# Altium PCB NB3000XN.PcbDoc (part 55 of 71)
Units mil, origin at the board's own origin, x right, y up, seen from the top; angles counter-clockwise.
Board outline 9527.56 x 6929.77 mil, 6 copper layers (Top Layer, GND+SHIELD, MidLayer1, MidLayer2, P2 - 3V3+5V0, Bottom Layer), stack 62.375 mil thick; 832 components, 1027 nets, 4655 pads, 4981 vias.
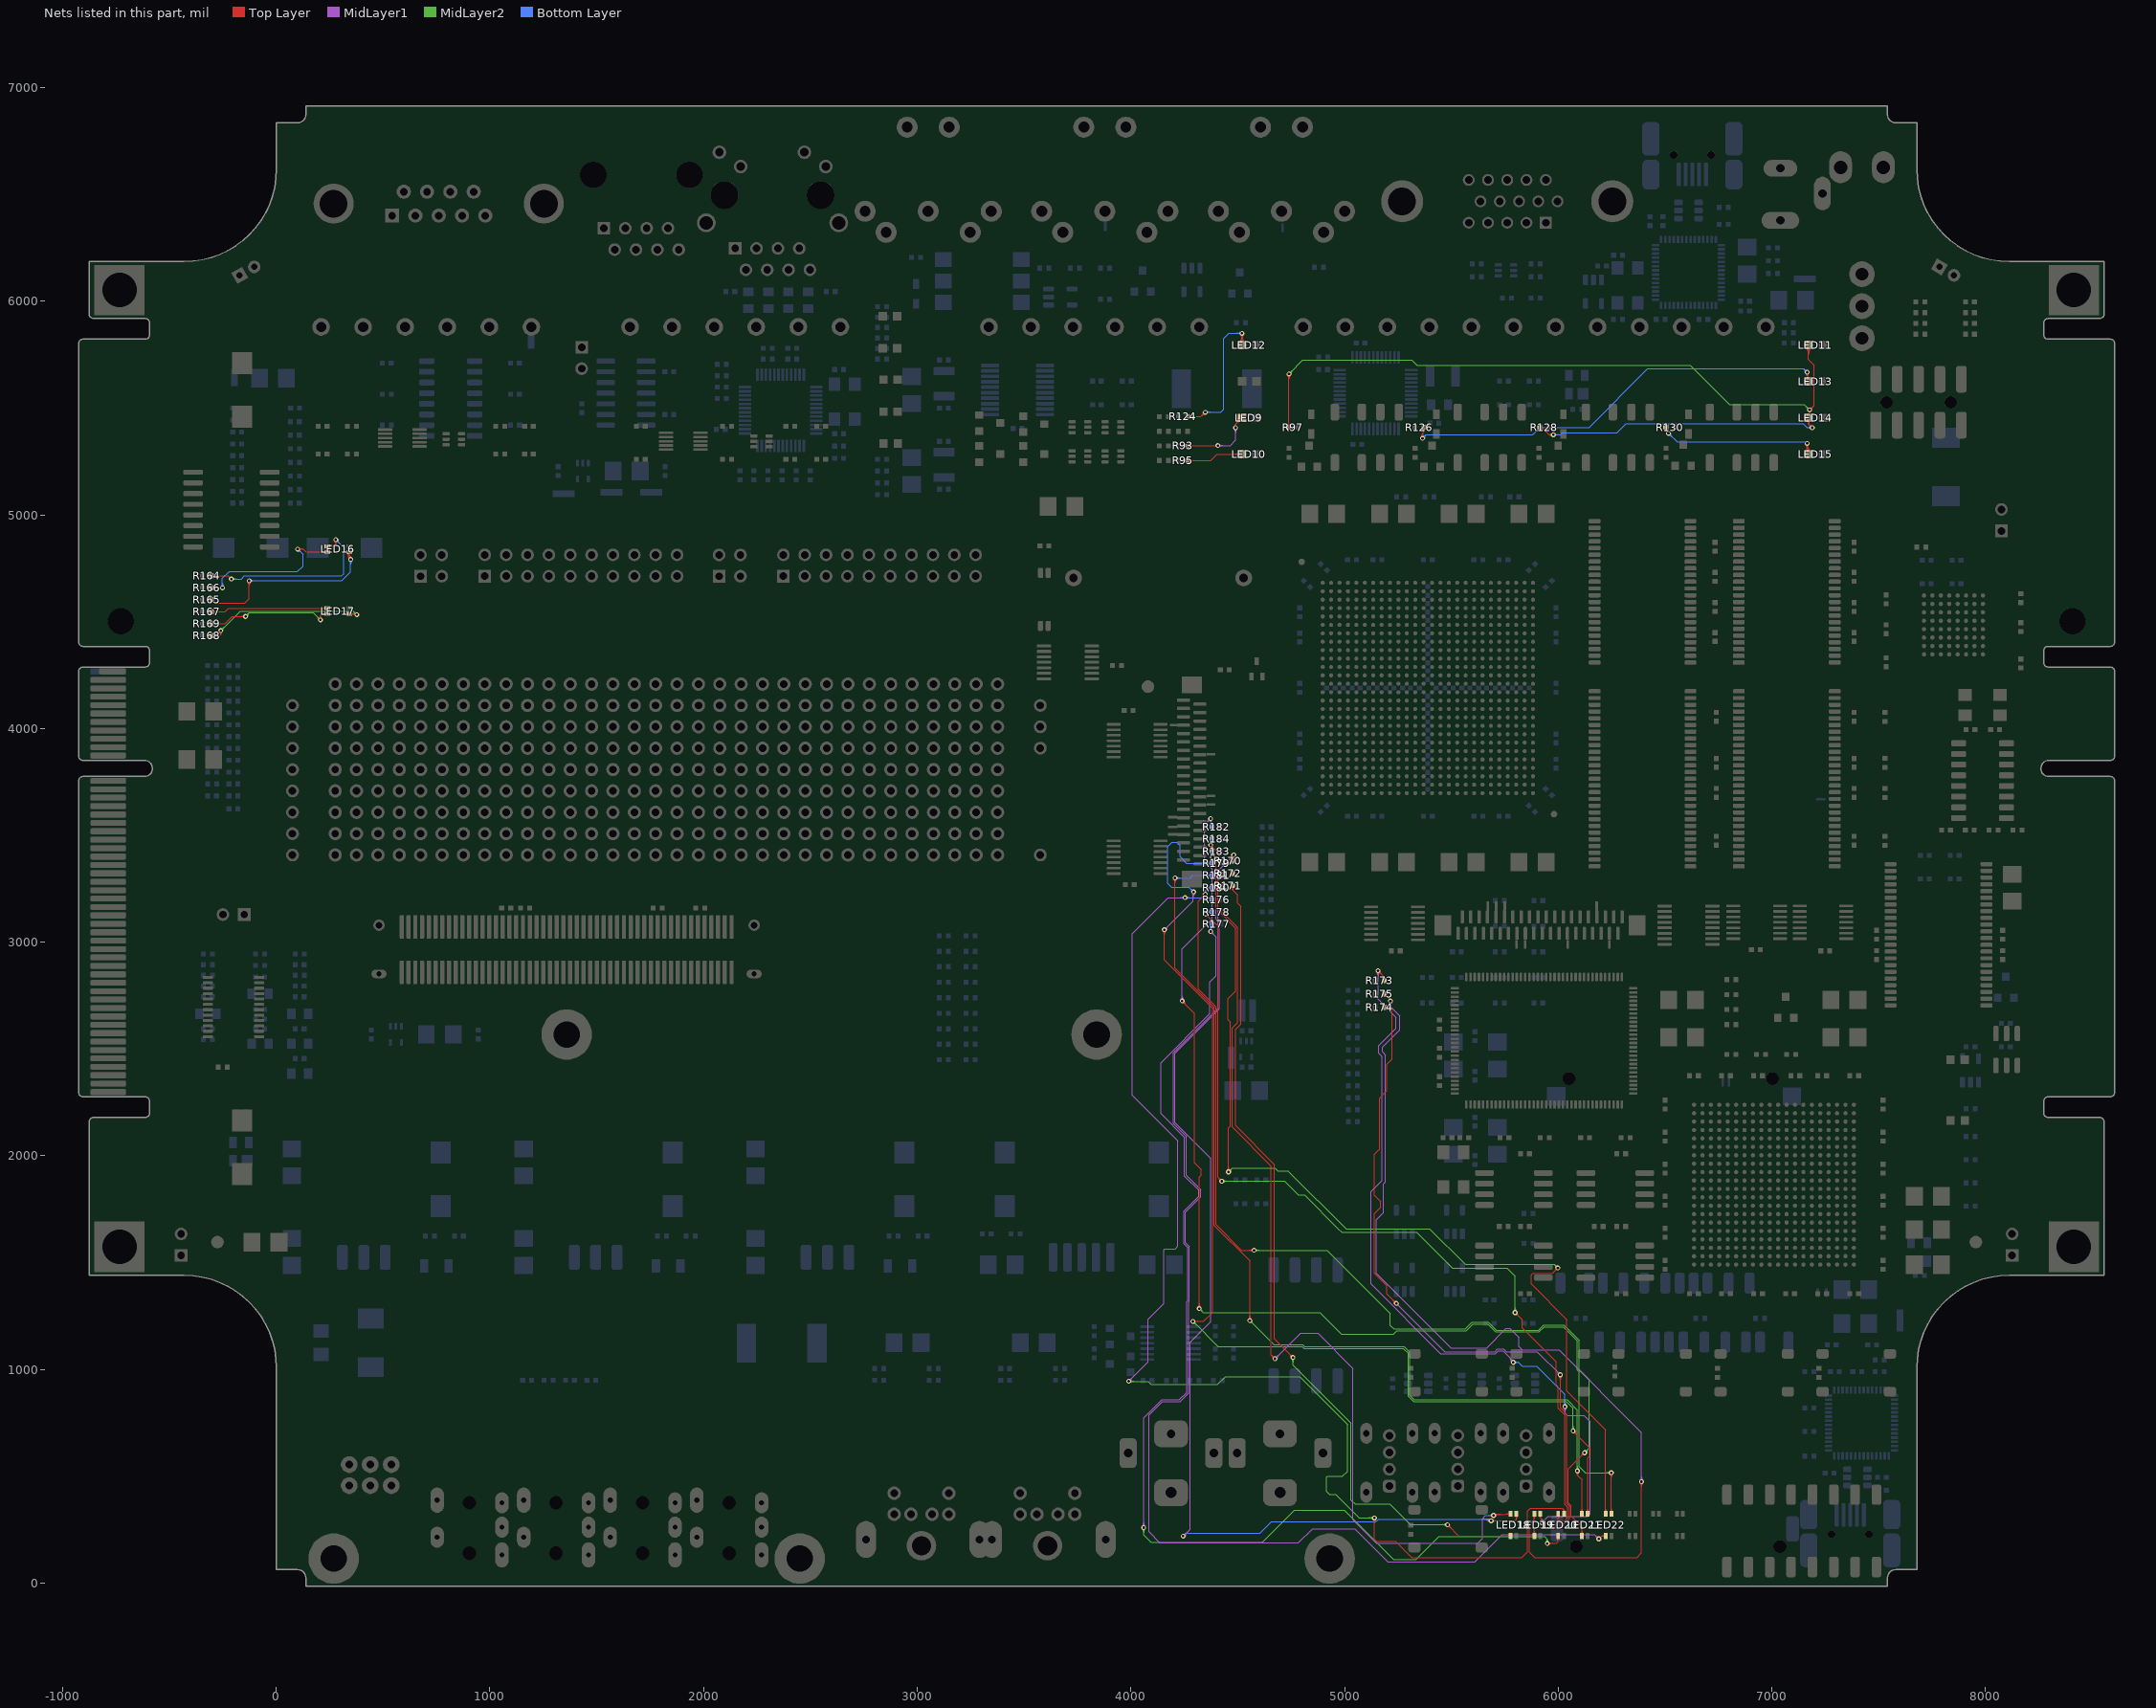
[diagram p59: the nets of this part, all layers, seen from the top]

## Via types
v1: diameter 23, hole 11.81, Top Layer to Bottom Layer, 3672 vias
v2: diameter 26, hole 11.81, Top Layer to Bottom Layer, 461 vias
v3: diameter 19, hole 11.81, Top Layer to Bottom Layer, tented both sides, 396 vias
v4: diameter 23.62, hole 11.81, Top Layer to Bottom Layer, 288 vias
v5: diameter 20, hole 11.81, Top Layer to Bottom Layer, 91 vias
v6: diameter 23, hole 11.81, Top Layer to Bottom Layer, tented both sides, 50 vias
v7: diameter 31, hole 11.81, Top Layer to Bottom Layer, 15 vias
v8: diameter 27.56, hole 11.81, Top Layer to Bottom Layer, tented both sides, 4 vias
v9: diameter 29, hole 11.81, Top Layer to Bottom Layer, 3 vias
v10: diameter 21, hole 11.81, Top Layer to Bottom Layer, 1 vias

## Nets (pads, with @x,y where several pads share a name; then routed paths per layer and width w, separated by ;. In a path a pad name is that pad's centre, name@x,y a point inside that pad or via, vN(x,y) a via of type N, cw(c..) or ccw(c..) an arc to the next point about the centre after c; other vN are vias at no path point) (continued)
NetLED9_2: LED9.2 R93.2 | length 677
  Top Layer w4: R93.2@4266.18,5323.33 4390.86,5323.33 4392.57,5325.04 v1(4406.86,5325.04) ; R93.2@4269.94,5319.57 cw(c4279.02,5310.49) 4279.02,5323.33 cw(c4279.02,5336.18) R93.2@4269.94,5327.09 ; R93.2@4272.77,5316.74 cw(c4288.68,5300.84) 4288.68,5323.33 cw(c4288.68,5345.83) R93.2@4272.77,5329.92 ; v1(4490.19,5408.37) 4490.19,5424.22 LED9.2@4520.49,5454.52 ; LED9.2@4502.8,5454.52 cw(c4460.1,5454.52) 4490.29,5424.33 cw(c4520.49,5394.14) LED9.2@4520.49,5436.83 ; LED9.2@4506.8,5454.52 cw(c4473.76,5454.52) 4497.12,5431.15 cw(c4520.49,5407.79) LED9.2@4520.49,5440.83 ; LED9.2@4510.8,5454.52 cw(c4487.42,5454.52) 4503.95,5437.98 cw(c4520.49,5421.45) LED9.2@4520.49,5444.83
  MidLayer1 w4: v1(4406.86,5325.04) 4465.04,5325.04 4490.19,5350.19 v1(4490.19,5408.37) ; v1@4410.75,5321.15 cw(c4420.14,5311.76) 4420.14,5325.04 cw(c4420.14,5338.32) v1@4410.75,5328.93 ; v1@4413.57,5318.32 cw(c4429.79,5302.11) 4429.79,5325.04 cw(c4429.79,5347.98) v1@4413.57,5331.76 ; v1@4483.47,5401.66 cw(c4467.26,5385.44) 4490.19,5385.44 cw(c4513.13,5385.44) v1@4496.91,5401.66 ; v1@4486.3,5404.49 cw(c4476.91,5395.1) 4490.19,5395.1 cw(c4503.47,5395.1) v1@4494.08,5404.49
NetLED10_2: LED10.2 R95.2 | length 477.6
  Top Layer w4: R95.2@4266.18,5255 4373.52,5255 4402.65,5284.13 LED10.2@4520.49,5284.13 ; R95.2@4269.94,5251.24 cw(c4279.02,5242.16) 4279.02,5255 cw(c4279.02,5267.84) R95.2@4269.94,5258.76 ; R95.2@4272.77,5248.41 cw(c4288.68,5232.5) 4288.68,5255 cw(c4288.68,5277.5) R95.2@4272.77,5261.59 ; LED10.2@4507.98,5271.63 ccw(c4477.79,5241.44) 4477.79,5284.13 ccw(c4477.79,5326.83) LED10.2@4507.98,5296.64 ; LED10.2@4510.81,5274.45 ccw(c4487.45,5251.09) 4487.45,5284.13 ccw(c4487.45,5317.17) LED10.2@4510.81,5293.81 ; LED10.2@4513.64,5277.28 ccw(c4497.1,5260.75) 4497.1,5284.13 ccw(c4497.1,5307.51) LED10.2@4513.64,5290.98
NetLED11_2: LED11.2 R97.2 | length 3566.2
  Top Layer w4: R97.2@4732.23,5417.08 ccw(c4713.01,5436.3) 4740.19,5436.3 ; v1@4733.47,5652.66 cw(c4717.26,5636.44) 4740.19,5636.44 cw(c4763.13,5636.44) v1@4746.91,5652.66 ; R97.2@4735.06,5414.25 ccw(c4722.67,5426.64) 4740.19,5426.64 ; v1@4736.3,5655.49 cw(c4726.91,5646.1) 4740.19,5646.1 cw(c4753.47,5646.1) v1@4744.08,5655.49 ; R97.2@4738.82,5410 4740.19,5411.37 v1(4740.19,5659.37) ; 4740.19,5429.68 ccw(c4758.01,5429.68) R97.2@4745.41,5417.08 ; LED11.2@7159.69,5782.78 cw(c7129.5,5752.59) 7172.19,5752.59 cw(c7214.89,5752.59) LED11.2@7184.7,5782.78 ; LED11.2@7162.52,5785.61 cw(c7139.15,5762.25) 7172.19,5762.25 cw(c7205.23,5762.25) LED11.2@7181.87,5785.61 ; LED11.2@7165.34,5788.44 cw(c7148.81,5771.9) 7172.19,5771.9 cw(c7195.57,5771.9) LED11.2@7179.04,5788.44 ; LED11.2@7172.19,5795.28 7172.19,5726.33 7198.52,5700 7198.52,5513.37 v1(7176.86,5491.71) ; v1@7176.86,5497.21 ccw(c7176.86,5510.49) 7186.25,5501.1 ccw(c7195.64,5491.71) v1@7182.36,5491.71 ; v1@7176.86,5501.21 ccw(c7176.86,5524.14) 7193.07,5507.93 ccw(c7209.29,5491.71) v1@7186.36,5491.71
  MidLayer2 w4: v1(4740.19,5659.37) 4775.41,5694.59 ; v1@4740.19,5664.87 ccw(c4740.19,5678.15) 4749.58,5668.76 ccw(c4758.97,5659.37) v1@4745.69,5659.37 ; v1@4740.19,5668.87 ccw(c4740.19,5691.81) 4756.41,5675.59 ccw(c4772.63,5659.37) v1@4749.69,5659.37 ; 4775,5695 4804.71,5724.71 4875,5724.71 5315.52,5724.71 5340.19,5700.04 6617.58,5700.04 6784.87,5532.75 6800.58,5517.04 7151.52,5517.04 v1(7176.86,5491.71) ; v1@7167.36,5491.71 ccw(c7144.42,5491.71) 7160.64,5507.93 ccw(c7176.86,5524.14) v1@7176.86,5501.21 ; v1@7171.36,5491.71 ccw(c7158.08,5491.71) 7167.47,5501.1 ccw(c7176.86,5510.49) v1@7176.86,5497.21
NetLED12_2: LED12.2 R124.2 | length 1107.1
  Top Layer w4: R124.2@4266.18,5460 4328.15,5460 v1(4348.52,5480.37) ; R124.2@4269.94,5456.24 cw(c4279.02,5447.16) 4279.02,5460 cw(c4279.02,5472.84) R124.2@4269.94,5463.76 ; R124.2@4272.77,5453.41 cw(c4288.68,5437.5) 4288.68,5460 cw(c4288.68,5482.5) R124.2@4272.77,5466.59 ; v1@4339.02,5480.37 cw(c4316.09,5480.37) 4332.31,5464.16 cw(c4348.52,5447.94) v1@4348.52,5470.87 ; v1@4343.02,5480.37 cw(c4329.75,5480.37) 4339.14,5470.99 cw(c4348.52,5461.6) v1@4348.52,5474.87 ; LED12.2@4507.98,5807.8 ccw(c4476.82,5838.96) v1@4520.89,5838.96 ; LED12.2@4510.81,5804.97 ccw(c4486.47,5829.3) 4520.89,5829.3 ; v1@4513.28,5843.28 cw(c4494.92,5824.92) 4520.89,5824.92 ; LED12.2@4513.64,5802.14 ccw(c4496.13,5819.65) 4520.89,5819.65 ; v1@4516.11,5846.11 cw(c4504.58,5834.58) 4520.89,5834.58 ; v1(4520,5850) 4520.89,5849.11 4520.89,5789.18 4520.49,5789.18 LED12.2@4520.49,5795.29 ; 4520.89,5817.7 ccw(c4542.89,5817.7) LED12.2@4527.33,5802.14 ; 4520.89,5827.35 ccw(c4552.55,5827.35) LED12.2@4530.16,5804.97 ; 4520.89,5829.21 cw(c4540.79,5829.21) v1@4526.72,5843.28 ; 4520.89,5837.01 ccw(c4562.21,5837.01) LED12.2@4532.99,5807.8
  Bottom Layer w4: v1(4348.52,5480.37) 4420.41,5480.37 4435.04,5495 4435.04,5825.04 4460,5850 v1(4520,5850) ; v1@4352.41,5476.49 cw(c4361.8,5467.1) 4361.8,5480.37 cw(c4361.8,5493.65) v1@4352.41,5484.26 ; v1@4355.24,5473.66 cw(c4371.46,5457.44) 4371.46,5480.37 cw(c4371.46,5503.31) v1@4355.24,5487.09 ; v1@4513.28,5843.28 ccw(c4497.06,5827.06) 4497.06,5850 ccw(c4497.06,5872.93) v1@4513.28,5856.72 ; v1@4516.11,5846.11 ccw(c4506.72,5836.72) 4506.72,5850 ccw(c4506.72,5863.28) v1@4516.11,5853.89
NetLED13_2: LED13.2 R126.2 | length 2359.2
  Top Layer w4: v1@5358.47,5365.09 ccw(c5342.26,5381.31) 5365.19,5381.31 ccw(c5388.13,5381.31) v1@5371.91,5365.09 ; v1@5361.3,5362.26 ccw(c5351.91,5371.65) 5365.19,5371.65 ccw(c5378.47,5371.65) v1@5369.08,5362.26 ; R126.2@5364.98,5402.56 cw(c5352.61,5388.7) 5371.18,5388.7 ; v1(5365.19,5358.37) 5365.19,5382.71 5371.18,5388.7 ; R126.2@5367.64,5405.54 cw(c5360.58,5397.63) 5371.18,5397.63 cw(c5381.78,5397.63) R126.2@5374.72,5405.54 ; R126.2@5371.18,5410 5371.18,5388.7 ; R126.2@5377.39,5402.56 ccw(c5389.76,5388.7) 5371.18,5388.7 ; v1@7160.64,5659.37 cw(c7156.47,5651.71) 7165.19,5651.71 ; v1(7165.19,5667.71) 7165.19,5651.71 ; 7165.44,5651.46 cw(c7152.53,5638.55) LED13.2@7167.52,5628.14 ; 7168.82,5648.08 cw(c7156.52,5635.78) LED13.2@7170.81,5625.86 ; v1@7169.74,5659.37 ccw(c7173.91,5651.71) 7165.19,5651.71 ; LED13.2@7170.2,5642.47 ccw(c7169.94,5644.71) 7172.19,5644.71 ; LED13.2@7172.19,5624.9 7172.19,5644.71 ; 7172.21,5644.69 cw(c7160.52,5633.01) LED13.2@7174.09,5623.58 ; LED13.2@7174.19,5642.47 cw(c7174.44,5644.71) 7172.19,5644.71 ; 7165.19,5651.71 7172.19,5644.71
  Bottom Layer w4: v1(5365.19,5358.37) 5381.86,5375.04 5881.86,5375.04 5916.19,5409.37 6144.37,5409.37 6419.04,5684.04 6825,5684.04 7148.86,5684.04 v1(7165.19,5667.71) ; v1@5365.19,5363.87 ccw(c5365.19,5377.15) 5374.58,5367.76 ccw(c5383.97,5358.37) v1@5370.69,5358.37 ; v1@5365.19,5367.87 ccw(c5365.19,5390.81) 5381.41,5374.59 ccw(c5397.63,5358.37) v1@5374.69,5358.37 ; v1@7155.69,5667.71 ccw(c7132.76,5667.71) 7148.97,5683.93 ccw(c7165.19,5700.14) v1@7165.19,5677.21 ; v1@7159.69,5667.71 ccw(c7146.41,5667.71) 7155.8,5677.1 ccw(c7165.19,5686.49) v1@7165.19,5673.21
NetLED14_2: LED14.2 R128.2 | length 1728.7
  Top Layer w4: R128.2@5913.82,5400.19 cw(c5913.82,5357) 5944.36,5387.54 ; R128.2@5913.82,5404.19 cw(c5913.82,5370.65) 5937.53,5394.37 ; R128.2@5913.82,5408.19 cw(c5913.82,5384.31) 5930.7,5401.19 ; R128.2@5913.82,5410 5921.9,5410 5956.86,5375.04 ; v1@5969.9,5368.95 ccw(c5956.86,5358.03) 5956.86,5375.04 ; v1@5969.9,5381.14 cw(c5956.86,5392.05) 5956.86,5375.04 ; v1@5972.97,5371.51 ccw(c5965.42,5365.19) 5965.42,5375.04 ccw(c5965.42,5384.89) v1@5972.97,5378.57 ; v1(5977.19,5375.04) 5956.86,5375.04 ; LED14.2@7163.87,5438.91 cw(c7156.48,5425.04) 7172.19,5425.04 ; LED14.2@7165.75,5442.44 cw(c7160.03,5431.71) 7172.19,5431.71 cw(c7184.35,5431.71) LED14.2@7178.63,5442.44 ; LED14.2@7172.19,5454.51 7172.19,5425.04 ; v1@7179.36,5408.37 ccw(c7156.42,5408.37) 7172.64,5424.59 ccw(c7188.86,5440.81) v1@7188.86,5417.87 ; LED14.2@7180.51,5438.91 ccw(c7187.91,5425.04) 7172.19,5425.04 ; v1@7183.36,5408.37 ccw(c7170.08,5408.37) 7179.47,5417.76 ccw(c7188.86,5427.15) v1@7188.86,5413.87 ; v1(7188.86,5408.37) 7172.19,5425.04
  Bottom Layer w4: v1(5977.19,5375.04) 6010,5375.04 6020.33,5385.37 6275.52,5385.37 6317.15,5427 7146.37,5427 7165,5408.37 v1(7188.86,5408.37) ; v1@5981.08,5371.15 cw(c5990.47,5361.76) 5990.47,5375.04 cw(c5990.47,5388.32) v1@5981.08,5378.93 ; v1@5983.91,5368.32 cw(c6000.13,5352.11) 6000.13,5375.04 cw(c6000.13,5397.98) v1@5983.91,5381.76 ; v1@7182.14,5401.66 ccw(c7165.92,5385.44) 7165.92,5408.37 ccw(c7165.92,5431.31) v1@7182.14,5415.09 ; v1@7184.97,5404.49 ccw(c7175.58,5395.1) 7175.58,5408.37 ccw(c7175.58,5421.65) v1@7184.97,5412.26
NetLED15_2: LED15.2 R130.2 | length 1035.5
  Top Layer w4: R130.2@6499.48,5401.26 cw(c6495.71,5394.08) 6503.82,5394.08 ; R130.2@6503.82,5410 6503.82,5394.08 ; R130.2@6508.16,5401.26 ccw(c6511.93,5394.08) 6503.82,5394.08 ; v1(6515.86,5382.04) 6503.82,5394.08 ; v1@7158.47,5327.99 cw(c7142.26,5311.77) 7165.19,5311.77 cw(c7188.13,5311.77) v1@7171.91,5327.99 ; LED15.2@7159.69,5296.63 ccw(c7146.4,5309.91) 7165.19,5309.91 ; v1@7161.3,5330.82 cw(c7151.91,5321.43) 7165.19,5321.43 cw(c7178.47,5321.43) v1@7169.08,5330.82 ; 7165.19,5310.12 ccw(c7192.48,5310.12) LED15.2@7175.69,5288.61 ; 7165.19,5318.31 ccw(c7198.87,5318.31) LED15.2@7178.15,5291.76 ; v1@7165.19,5326.51 ccw(c7205.27,5326.51) LED15.2@7180.61,5294.91 ; LED15.2@7172.19,5284.12 7165.19,5291.13 v1(7165.19,5334.71) ccw(c7211.66,5334.71) LED15.2@7183.07,5298.07
  Bottom Layer w4: v1@6515.86,5372.54 cw(c6515.86,5349.61) 6532.07,5365.82 cw(c6548.29,5382.04) v1@6525.36,5382.04 ; v1@6515.86,5376.54 cw(c6515.86,5363.26) 6525.25,5372.65 cw(c6534.64,5382.04) v1@6521.36,5382.04 ; v1(6515.86,5382.04) 6556.52,5341.37 7158.63,5341.37 v1@7165,5335 ; v1@7164.95,5334.95 v1(7165.19,5334.71)
NetLED16_1: LED16.1 R164.1 | length 1124.1
  Top Layer w4: R164.1@-303.82,4715 -224.77,4715 v1(-209.81,4700.04) ; R164.1@-300.06,4711.24 cw(c-290.98,4702.16) -290.98,4715 cw(c-290.98,4727.84) R164.1@-300.06,4718.76 ; R164.1@-297.23,4708.41 cw(c-281.32,4692.5) -281.32,4715 cw(c-281.32,4737.5) R164.1@-297.23,4721.59 ; LED16.1@241.49,4853.78 270.86,4853.78 278.86,4861.78 ; LED16.1@248.38,4848.75 cw(c260.52,4836.61) 260.52,4853.78 ; LED16.1@248.38,4858.45 ccw(c259.66,4869.73) 259.66,4853.78 ; v1@272.21,4877.59 cw(c256.74,4861.78) 278.86,4861.78 ; v1@275.01,4880.44 cw(c266.05,4871.29) 278.86,4871.29 cw(c291.66,4871.29) v1@282.7,4880.44 ; v1(278.86,4884.37) 278.86,4861.78 ; v1@285.5,4877.59 ccw(c300.98,4861.78) 278.86,4861.78
  Bottom Layer w4: v1(-209.81,4700.04) -164,4700.04 -150,4714.04 304.19,4714.04 315.19,4725.04 315.19,4848.04 v1(278.86,4884.37) ; v1@-205.92,4696.15 cw(c-196.53,4686.76) -196.53,4700.04 cw(c-196.53,4713.32) v1@-205.92,4703.93 ; v1@-203.09,4693.32 cw(c-186.87,4677.11) -186.87,4700.04 cw(c-186.87,4722.98) v1@-203.09,4706.76 ; v1@278.86,4874.87 cw(c278.86,4851.94) 295.07,4868.16 cw(c311.29,4884.37) v1@288.36,4884.37 ; v1@278.86,4878.87 cw(c278.86,4865.6) 288.25,4874.99 cw(c297.64,4884.37) v1@284.36,4884.37
NetLED16_3: LED16.3 R165.1 | length 1255.6
  Top Layer w4: R165.1@-303.82,4603 -287.69,4586.87 -148.13,4586.87 -126.48,4608.52 v1(-126.48,4691.71) ; R165.1@-303.73,4597.19 cw(c-303.51,4583.91) R165.1@-294.12,4593.3 ; R165.1@-303.66,4593.19 cw(c-303.29,4570.78) -287.45,4586.63 ; R165.1@-298.5,4602.51 ccw(c-286.85,4602.51) R165.1@-295.09,4594.27 ; R165.1@-294.5,4602.51 ccw(c-273.19,4602.51) -288.26,4587.44 ; v1@-133.19,4684.99 cw(c-149.41,4668.77) -126.48,4668.77 cw(c-103.54,4668.77) v1@-119.76,4684.99 ; v1@-130.36,4687.82 cw(c-139.75,4678.43) -126.48,4678.43 cw(c-113.2,4678.43) v1@-122.59,4687.82 ; LED16.3@332.24,4821.55 cw(c315.61,4804.92) 339.13,4804.92 ; LED16.3@333.47,4820.56 cw(c319.81,4806.91) 339.13,4806.91 cw(c358.44,4806.91) LED16.3@344.79,4820.56 ; LED16.3@335.07,4824.38 cw(c325.26,4814.57) 339.13,4814.57 ; 339.13,4804.3 ccw(c356.58,4804.3) v1@347.18,4789.6 ; 339.13,4811.61 ccw(c361.25,4811.61) v1@349.33,4792.97 ; 339.13,4814.77 cw(c348.72,4814.77) LED16.3@341.94,4821.55 ; LED16.3@339.13,4818.91 ccw(c365.92,4818.91) v1@351.49,4796.34 ; v1(348.52,4791.71) 339.13,4801.1 339.13,4826.22 ccw(c370.59,4826.22) v1@353.64,4799.71
  Bottom Layer w4: v1(-126.48,4691.71) 306.86,4691.71 348.52,4733.37 v1(348.52,4791.71) ; v1@-122.59,4687.82 cw(c-113.2,4678.43) -113.2,4691.71 cw(c-113.2,4704.99) v1@-122.59,4695.6 ; v1@-119.76,4684.99 cw(c-103.54,4668.77) -103.54,4691.71 cw(c-103.54,4714.64) v1@-119.76,4698.43 ; v1@341.81,4784.99 cw(c325.59,4768.77) 348.52,4768.77 cw(c371.46,4768.77) v1@355.24,4784.99 ; v1@344.64,4787.82 cw(c335.25,4778.43) 348.52,4778.43 cw(c361.8,4778.43) v1@352.41,4787.82
NetLED16_4: LED16.4 R166.1 | length 986.6
  Top Layer w4: R166.1@-303.82,4659 -267.48,4659 ; R166.1@-300.06,4655.24 cw(c-290.98,4646.16) -290.98,4659 cw(c-290.98,4671.84) R166.1@-300.06,4662.76 ; R166.1@-297.23,4652.41 cw(c-281.32,4636.5) -281.32,4659 cw(c-281.32,4681.5) R166.1@-297.23,4665.59 ; -266.85,4658.37 v1(-251.48,4658.37) ; v1(100,4840) 100.12,4840.12 125.12,4840.12 139.01,4826.22 LED16.4@241.49,4826.22 ; v1@103.89,4836.11 cw(c113.56,4826.44) 113.56,4840.12 ; v1@103.89,4843.89 ccw(c113,4853) 113,4840.12 ; v1@106.72,4833.28 cw(c123.21,4816.79) 123.21,4840.12 ; v1@106.72,4846.72 ccw(c122.66,4862.66) 122.66,4840.12 ; 216.46,4826.22 ccw(c216.46,4843.73) LED16.4@228.84,4831.35 ; 217.81,4826.22 cw(c217.81,4810.62) LED16.4@228.84,4821.65
  Bottom Layer w4: v1@-258.19,4665.09 ccw(c-274.41,4681.31) -251.48,4681.31 ccw(c-228.54,4681.31) v1@-244.76,4665.09 ; v1@-255.36,4662.26 ccw(c-264.75,4671.65) -251.48,4671.65 ccw(c-238.2,4671.65) v1@-247.59,4662.26 ; v1(-251.48,4658.37) -251.48,4703.52 -220,4735 100,4735 125,4760 125,4815 v1(100,4840) ; v1@100,4830.5 cw(c100,4807.56) 116.22,4823.78 cw(c132.43,4840) v1@109.5,4840 ; v1@100,4834.5 cw(c100,4821.22) 109.39,4830.61 cw(c118.78,4840) v1@105.5,4840
NetLED17_1: LED17.1 R167.1 | length 633.8
  Top Layer w4: R167.1@-303.82,4547 -240,4547 -223.22,4563.78 LED17.1@241.49,4563.78 ; R167.1@-300.06,4543.24 cw(c-290.98,4534.16) -290.98,4547 cw(c-290.98,4559.84) R167.1@-300.06,4550.76 ; R167.1@-297.23,4540.41 cw(c-281.32,4524.5) -281.32,4547 cw(c-281.32,4569.5) R167.1@-297.23,4553.59 ; 216.7,4563.78 cw(c216.7,4546.61) LED17.1@228.84,4558.75 ; 217.56,4563.78 ccw(c217.56,4579.73) LED17.1@228.84,4568.45
NetLED17_3: LED17.3 R168.1 | length 1004
  Top Layer w4: R168.1@-303.82,4435 -265,4435 -259.81,4440.19 ; R168.1@-300.06,4431.24 cw(c-290.98,4422.16) -290.98,4435 cw(c-290.98,4447.84) R168.1@-300.06,4438.76 ; R168.1@-297.23,4428.41 cw(c-281.32,4412.5) -281.32,4435 cw(c-281.32,4457.5) R168.1@-297.23,4441.59 ; v1@-265.24,4450.58 cw(c-272.46,4440.19) -259.81,4440.19 ; v1(-259.81,4458.37) -259.81,4440.19 ; v1@-254.38,4450.58 ccw(c-247.16,4440.19) -259.81,4440.19 ; LED17.3@339.13,4536.22 363.01,4536.22 ; LED17.3@351.79,4531.56 cw(c363.01,4520.38) 363.01,4536.22 ; LED17.3@351.97,4541.05 ccw(c363.01,4551.25) 363.01,4536.22 ; v1(377.19,4533.37) 365.86,4533.37 363.01,4536.22
  MidLayer2 w4: v1(-259.81,4458.37) -168.14,4550.04 -80,4550.04 -50.04,4550 -50,4550.04 360.52,4550.04 v1(377.19,4533.37) ; v1@-259.81,4463.87 ccw(c-259.81,4477.15) -250.42,4467.76 ccw(c-241.03,4458.37) v1@-254.31,4458.37 ; v1@-259.81,4467.87 ccw(c-259.81,4490.81) -243.59,4474.59 ccw(c-227.37,4458.37) v1@-250.31,4458.37 ; v1@367.69,4533.37 ccw(c344.76,4533.37) 360.97,4549.59 ccw(c377.19,4565.81) v1@377.19,4542.87 ; v1@371.69,4533.37 ccw(c358.41,4533.37) 367.8,4542.76 ccw(c377.19,4552.15) v1@377.19,4538.87
NetLED17_4: LED17.4 R169.1 | length 884
  Top Layer w4: R169.1@-303.82,4491 -239,4491 -204.96,4525.04 v1(-143.14,4525.04) ; R169.1@-300.06,4487.24 cw(c-290.98,4478.16) -290.98,4491 cw(c-290.98,4503.84) R169.1@-300.06,4494.76 ; R169.1@-297.23,4484.41 cw(c-281.32,4468.5) -281.32,4491 cw(c-281.32,4513.5) R169.1@-297.23,4497.59 ; v1@-149.86,4518.32 ccw(c-166.08,4502.11) -166.08,4525.04 ccw(c-166.08,4547.98) v1@-149.86,4531.76 ; v1@-147.03,4521.15 ccw(c-156.42,4511.76) -156.42,4525.04 ccw(c-156.42,4538.32) v1@-147.03,4528.93 ; v1@200.9,4515.77 ccw(c190.88,4528.22) 206.86,4528.22 ; v1(206.86,4508.37) 206.86,4528.22 ; v1@212.81,4515.77 cw(c222.83,4528.22) 206.86,4528.22 ; 216.46,4536.22 ccw(c216.46,4553.73) LED17.4@228.84,4541.35 ; 217.81,4536.22 cw(c217.81,4520.62) LED17.4@228.84,4531.65 ; LED17.4@241.49,4536.22 214.86,4536.22 206.86,4528.22
  MidLayer2 w4: v1(-143.14,4525.04) -126.48,4541.71 173.52,4541.71 v1(206.86,4508.37) ; v1@-143.14,4530.54 ccw(c-143.14,4543.82) -133.75,4534.43 ccw(c-124.36,4525.04) v1@-137.64,4525.04 ; v1@-143.14,4534.54 ccw(c-143.14,4557.48) -126.93,4541.26 ccw(c-110.71,4525.04) v1@-133.64,4525.04 ; v1@197.36,4508.37 ccw(c174.42,4508.37) 190.64,4524.59 ccw(c206.86,4540.81) v1@206.86,4517.87 ; v1@201.36,4508.37 ccw(c188.08,4508.37) 197.47,4517.76 ccw(c206.86,4527.15) v1@206.86,4513.87
NetLED18_1: LED18.1 R170.1 | length 5504.3
  Top Layer w4: R170.1@4471.04,3388.27 ccw(c4457.76,3408.37) v1(4481.86,3408.37) R170.1@4481.86,3383.37 ; R170.1@4473.25,3384.93 ccw(c4462.67,3400.94) v1@4481.86,3400.94 ; v1@4475.14,3401.66 cw(c4458.92,3385.44) 4481.86,3385.44 cw(c4504.79,3385.44) v1@4488.57,3401.66 ; R170.1@4475.45,3381.59 ccw(c4467.59,3393.5) 4481.86,3393.5 ; v1@4477.97,3404.49 cw(c4468.58,3395.1) 4481.86,3395.1 cw(c4495.14,3395.1) v1@4485.75,3404.49 ; v1(5686.19,291.71) 5797.44,291.71 5804.73,299 LED18.1@5804.73,321.33 ; v1@5690.08,287.82 cw(c5699.47,278.43) 5699.47,291.71 cw(c5699.47,304.99) v1@5690.08,295.6 ; v1@5692.91,284.99 cw(c5709.13,268.77) 5709.13,291.71 cw(c5709.13,314.64) v1@5692.91,298.43 ; LED18.1@5799.71,314.44 cw(c5787.56,302.3) 5804.73,302.3 ; 5804.73,303.16 cw(c5820.68,303.16) LED18.1@5809.4,314.44
  MidLayer1 w4: v1(4245,220) 4278,253 4278,1128 4373.52,1223.52 4373.52,1987.73 4206.86,2154.4 4206.86,2480.39 4415,2688.54 4415,2730 ; v1@4245,225.5 ccw(c4245,238.78) 4254.39,229.39 ccw(c4263.78,220) v1@4250.5,220 ; v1@4245,229.5 ccw(c4245,252.43) 4261.22,236.22 ccw(c4277.43,220) v1@4254.5,220 ; 4415.19,2730 4415.19,3101.12 4406.86,3109.46 4406.86,3333.37 v1(4481.86,3408.37) ; v1@4472.36,3408.37 cw(c4449.42,3408.37) 4465.64,3392.16 cw(c4481.86,3375.94) v1@4481.86,3398.87 ; v1@4476.36,3408.37 cw(c4463.08,3408.37) 4472.47,3398.99 cw(c4481.86,3389.6) v1@4481.86,3402.87
  Bottom Layer w4: v1(4245,220) 4258.37,233.37 4604.69,233.37 4658.5,287.19 5147.38,287.19 5160.23,300.04 5677.86,300.04 v1(5686.19,291.71) ; 5643.14,300.04 cw(c5643.14,248.66) v1@5679.47,284.99 ; 5652.79,300.04 cw(c5652.79,258.31) v1@5682.3,287.82 ; 5662.45,300.04 cw(c5662.45,267.97) v1@5685.13,290.65 ; 5672.11,300.04 cw(c5672.11,277.63) v1@5687.96,293.48
NetLED18_3: LED18.3 R171.1 | length 4246.8
  Top Layer w4: R171.1@4469.9,3257.63 cw(c4456.88,3243.38) 4476.18,3243.38 ; R171.1@4472.59,3260.58 cw(c4465.17,3252.45) 4476.18,3252.45 cw(c4487.2,3252.45) R171.1@4479.77,3260.58 ; R171.1@4476.18,3265 4476.18,3243.37 ; R171.1@4482.47,3257.63 ccw(c4495.48,3243.38) 4476.18,3243.38 ; v1@4749.36,1056.37 ccw(c4726.42,1056.37) 4742.64,1072.59 ccw(c4758.86,1088.81) v1@4758.86,1065.87 ; v1@4753.36,1056.37 ccw(c4740.08,1056.37) 4749.47,1065.76 ccw(c4758.86,1075.15) v1@4758.86,1061.87 ; v1(4758.86,1056.37) 4672.71,1142.52 4672.71,1959.18 4490.19,2141.71 4490.19,2591.71 4515.19,2616.71 4515.19,3166.71 4498.52,3183.37 4498.52,3221.03 4476.18,3243.37 ; v1@5481.86,263.87 cw(c5481.86,240.94) 5498.07,257.16 cw(c5514.29,273.37) v1@5491.36,273.37 ; v1@5481.86,267.87 cw(c5481.86,254.6) 5491.25,263.99 cw(c5500.64,273.37) v1@5487.36,273.37 ; v1(5481.86,273.37) 5534.42,220.81 LED18.3@5777.35,220.81 ; LED18.3@5772.51,215.96 ccw(c5760.8,204.25) 5760.8,220.81 ccw(c5760.8,237.36) LED18.3@5772.51,225.66
  MidLayer2 w4: v1@4752.14,1049.66 cw(c4735.92,1033.44) 4758.86,1033.44 cw(c4781.79,1033.44) v1@4765.57,1049.66 ; v1@4754.97,1052.49 cw(c4745.58,1043.1) 4758.86,1043.1 cw(c4772.14,1043.1) v1@4762.75,1052.49 ; v1(4758.86,1056.37) 4758.86,1021.14 5030,750 5030,389.43 5049.43,370 5212.25,370 5308.88,273.37 v1(5481.86,273.37) ; v1@5475.14,266.66 ccw(c5458.92,250.44) 5458.92,273.37 ccw(c5458.92,296.31) v1@5475.14,280.09 ; v1@5477.97,269.49 ccw(c5468.58,260.1) 5468.58,273.37 ccw(c5468.58,286.65) v1@5477.97,277.26
NetLED18_4: LED18.4 R172.1 | length 4925.2
  Top Layer w4: 4459.43,3305.75 cw(c4476.18,3289) R172.1@4476.18,3312.69 ; 4460.62,3306.94 ccw(c4445.55,3322.01) R172.1@4466.86,3322.01 ; R172.1@4466.26,3312.58 cw(c4476.18,3302.66) R172.1@4476.18,3316.69 ; R172.1@4467.45,3313.77 ccw(c4459.21,3322.01) R172.1@4470.86,3322.01 ; R172.1@4476.18,3322.5 4453.72,3300.04 4416.86,3300.04 4406.86,3290.04 4406.86,3161.36 4499.19,3069.02 4499.19,2623.34 4473.86,2598 4473.86,2135.41 4656.71,1952.56 4656.71,1067.85 v1(4674.52,1050.04) ; v1@4665.02,1050.04 ccw(c4642.09,1050.04) 4658.31,1066.26 ccw(c4674.52,1082.48) v1@4674.52,1059.54 ; v1@4669.02,1050.04 ccw(c4655.75,1050.04) 4665.14,1059.43 ccw(c4674.52,1068.82) v1@4674.52,1055.54 ; v1(5697.52,316.71) 5702.14,321.33 5750,321.33 5752.88,324.21 LED18.4@5777.45,324.21 ; v1@5698.58,315.65 cw(c5712.29,301.94) 5712.29,321.33 ; v1@5701.41,312.82 cw(c5721.95,292.28) 5721.95,321.33 ; v1@5704.24,309.99 cw(c5731.61,282.62) 5731.61,321.33 ; v1@5704.24,323.43 ccw(c5709.31,328.49) 5709.31,321.33 ; LED18.4@5772.61,319.36 ccw(c5760.9,307.65) 5760.9,324.21 ccw(c5760.9,340.76) LED18.4@5772.61,329.06
  MidLayer1 w4: v1(4674.52,1050.04) 4794.48,1170 4875.58,1170 5040.19,1005.39 5040.19,297.44 5149.82,187.81 5530,187.81 ; v1@4674.52,1055.54 ccw(c4674.52,1068.82) 4683.91,1059.43 ccw(c4693.3,1050.04) v1@4680.02,1050.04 ; v1@4674.52,1059.54 ccw(c4674.52,1082.48) 4690.74,1066.26 ccw(c4706.96,1050.04) v1@4684.02,1050.04 ; 5590,187.81 5530,187.81 ; v1@5690.81,309.99 ccw(c5674.59,293.77) 5674.59,316.71 ccw(c5674.59,339.64) v1@5690.81,323.43 ; v1@5693.64,312.82 ccw(c5684.25,303.43) 5684.25,316.71 ccw(c5684.25,329.99) v1@5693.64,320.6 ; v1(5697.52,316.71) 5660,316.71 5645,301.71 5645,210 5622.81,187.81 5530,187.81
NetLED19_1: LED19.1 R173.1 | length 4150.4
  Top Layer w4: v1@5156.86,2857.21 cw(c5156.86,2834.27) 5173.07,2850.49 cw(c5189.29,2866.71) v1@5166.36,2866.71 ; v1@5156.86,2861.21 cw(c5156.86,2847.93) 5166.25,2857.32 cw(c5175.64,2866.71) v1@5162.36,2866.71 ; v1(5156.86,2866.71) 5186.18,2837.38 ; R173.1@5181.21,2828.38 ccw(c5175.53,2837.38) 5186.18,2837.38 ; R173.1@5186.18,2820 5186.18,2837.38 ; R173.1@5191.15,2828.38 cw(c5196.83,2837.38) 5186.18,2837.38 ; LED19.1@5912.51,313.27 cw(c5909.48,307.72) 5915.8,307.72 ; LED19.1@5915.8,324.21 5915.8,307.72 ; LED19.1@5919.09,313.27 ccw(c5922.12,307.72) 5915.8,307.72 ; v1(5923.52,283.37) 5923.52,300 5915.8,307.72
  MidLayer1 w4: v1@5150.14,2859.99 cw(c5133.92,2843.77) 5156.86,2843.77 cw(c5179.79,2843.77) v1@5163.57,2859.99 ; v1@5152.97,2862.82 cw(c5143.58,2853.43) 5156.86,2853.43 cw(c5170.14,2853.43) v1@5160.75,2862.82 ; v1(5156.86,2866.71) 5156.86,2734.04 5241.81,2649.09 5241.81,2595.62 5161.19,2515 5161.19,2480.04 5176.4,2464.83 5176.4,1885.16 5123.86,1832.61 5123.86,1399.71 5449.02,1074.55 5706.25,1074.55 5719.74,1088.04 5742.25,1088.04 5790.19,1040.1 v1(5790.19,1033.37) ; 5769.22,1061.07 cw(c5741.52,1033.37) v1@5780.69,1033.37 ; 5776.05,1054.24 cw(c5755.18,1033.37) v1@5784.69,1033.37 ; 5782.87,1047.41 cw(c5768.83,1033.37) v1@5788.69,1033.37 ; 5785.45,1044.84 ccw(c5790.19,1049.58) v1@5790.19,1042.87 ; v1(5923.52,283.37) 5953.19,313.04 6138.04,313.04 6148.86,323.86 6148.86,756.14 6120,785 6041.86,785 6031.86,795 v1(6031.86,826.04) ; v1@5923.52,288.87 ccw(c5923.52,302.15) 5932.91,292.76 ccw(c5942.3,283.37) v1@5929.02,283.37 ; v1@5923.52,292.87 ccw(c5923.52,315.81) 5939.74,299.59 ccw(c5955.96,283.37) v1@5933.02,283.37 ; v1@6025.14,819.32 cw(c6008.92,803.11) 6031.86,803.11 cw(c6054.79,803.11) v1@6038.57,819.32 ; v1@6027.97,822.15 cw(c6018.58,812.76) 6031.86,812.76 cw(c6045.14,812.76) v1@6035.75,822.15
  Bottom Layer w4: v1(5790.19,1033.37) 5813.97,1033.37 5832.35,1015 5900,1015 6031.86,883.14 v1(6031.86,826.04) ; v1@5794.08,1029.49 cw(c5803.47,1020.1) 5803.47,1033.37 cw(c5803.47,1046.65) v1@5794.08,1037.26 ; v1@5796.91,1026.66 cw(c5813.13,1010.44) 5813.13,1033.37 cw(c5813.13,1056.31) v1@5796.91,1040.09 ; v1@6025.14,832.76 ccw(c6008.92,848.98) 6031.86,848.98 ccw(c6054.79,848.98) v1@6038.57,832.76 ; v1@6027.97,829.93 ccw(c6018.58,839.32) 6031.86,839.32 ccw(c6045.14,839.32) v1@6035.75,829.93
NetLED19_3: LED19.3 R174.1 | length 3656.3
  Top Layer w4: R174.1@5186.18,2695 5215.86,2695 5223.86,2687 5223.86,2453.36 5198.52,2428.02 5198.52,2305 5164,2270.48 5164,2031.56 5139.86,2007.41 5139.86,1815.14 5170,1785 5170,1760 5139.86,1729.86 5139.86,1450.14 5198.52,1391.48 5198.52,1353.37 v1(5242.19,1309.71) ; R174.1@5189.94,2691.24 cw(c5199.02,2682.16) 5199.02,2695 cw(c5199.02,2707.84) R174.1@5189.94,2698.76 ; R174.1@5192.77,2688.41 cw(c5208.68,2672.5) 5208.68,2695 cw(c5208.68,2717.5) R174.1@5192.77,2701.59 ; v1@5232.69,1309.71 ccw(c5209.76,1309.71) 5225.97,1325.93 ccw(c5242.19,1342.14) v1@5242.19,1319.21 ; v1@5236.69,1309.71 ccw(c5223.41,1309.71) 5232.8,1319.1 ccw(c5242.19,1328.49) v1@5242.19,1315.21 ; LED19.3@5883.75,230.58 ccw(c5872.04,242.29) 5888.6,242.29 ccw(c5905.16,242.29) LED19.3@5893.45,230.58 ; LED19.3@5888.42,220.81 LED19.3@5888.42,223.69 ; LED19.3@5888.6,220.81 5888.6,253.6 5895,260 6009,260 6053,304 6053,359.25 6040,372.25 6040,790.19 6010.19,820 v1(6010.19,975.04) ; v1@6003.47,968.32 cw(c5987.26,952.11) 6010.19,952.11 cw(c6033.13,952.11) v1@6016.91,968.32 ; v1@6006.3,971.15 cw(c5996.91,961.76) 6010.19,961.76 cw(c6023.47,961.76) v1@6014.08,971.15
  MidLayer1 w4: v1@5242.19,1300.21 cw(c5242.19,1277.27) 5258.41,1293.49 cw(c5274.63,1309.71) v1@5251.69,1309.71 ; v1@5242.19,1304.21 cw(c5242.19,1290.93) 5251.58,1300.32 cw(c5260.97,1309.71) v1@5247.69,1309.71 ; v1(5242.19,1309.71) 5468.52,1083.37 5703.76,1083.37 5716.43,1096.04 5745.56,1096.04 5758.23,1083.37 5901.86,1083.37 v1(6010.19,975.04) ; v1@6000.69,975.04 ccw(c5977.76,975.04) 5993.97,991.26 ccw(c6010.19,1007.48) v1@6010.19,984.54 ; v1@6004.69,975.04 ccw(c5991.41,975.04) 6000.8,984.43 ccw(c6010.19,993.82) v1@6010.19,980.54
NetLED19_4: LED19.4 R175.1 | length 4682.8
  Top Layer w4: R175.1@5186.18,2747.69 cw(c5186.18,2712.21) 5211.27,2737.3 ; R175.1@5186.18,2751.69 cw(c5186.18,2725.87) 5204.44,2744.13 ; R175.1@5186.18,2755.69 cw(c5186.18,2739.53) 5197.61,2750.95 ; R175.1@5186.18,2757.5 5186.18,2750.04 5198.52,2750.04 5215.19,2733.37 v1(5215.19,2725.04) ; R175.1@5188.75,2752.35 cw(c5192.28,2745.95) R175.1@5197.45,2751.12 ; R175.1@5190.68,2748.85 cw(c5194.95,2741.09) 5201.21,2747.35 ; 5200.85,2747.71 cw(c5179.47,2726.32) v1@5209.69,2725.24 ; 5207.35,2741.21 cw(c5192.01,2725.87) v1@5213.69,2725.09 ; LED19.4@5883.85,314.44 cw(c5872.82,303.4) 5888.42,303.4 ; 5888.42,302.05 cw(c5905.93,302.05) LED19.4@5893.55,314.44 ; LED19.4@5888.42,321.33 5888.42,298.23 5865.19,275 5865.19,145 5890.19,120 6368.69,120 6390.19,141.5 v1(6390.19,475.04) ; v1@6383.47,468.32 cw(c6367.26,452.11) 6390.19,452.11 cw(c6413.13,452.11) v1@6396.91,468.32 ; v1@6386.3,471.15 cw(c6376.91,461.76) 6390.19,461.76 cw(c6403.47,461.76) v1@6394.08,471.15 ; R175.1@5195.5,2757.01 ccw(c5205.02,2757.01) 5198.29,2750.28 cw(c5205.02,2757.01) R175.1@5195.5,2757.01
  MidLayer1 w4: v1@5208.47,2718.32 cw(c5192.71,2702.56) 5215,2702.56 ; v1@5211.3,2721.15 cw(c5202.37,2712.22) 5215,2712.22 ; 5215,2701.65 cw(c5238.58,2701.65) v1@5221.91,2718.32 ; 5215,2711.3 cw(c5228.93,2711.3) v1@5219.08,2721.15 ; v1@5215,2725 5215,2698.52 5257.81,2655.71 5257.81,2588.99 5177.19,2508.37 5177.19,2486.67 5192.4,2471.45 5192.4,1878.53 5181.86,1867.98 5181.86,1733.37 5148.52,1700.04 5148.52,1450.04 5498.52,1100.04 5665.19,1100.04 5756.86,1191.71 5773.52,1191.71 5815.19,1150.04 5815.19,1108.37 5831.86,1091.71 6003.88,1091.71 6390.19,705.39 v1(6390.19,475.04) ; v1@6383.47,481.76 ccw(c6367.26,497.98) 6390.19,497.98 ccw(c6413.13,497.98) v1@6396.91,481.76 ; v1@6386.3,478.93 ccw(c6376.91,488.32) 6390.19,488.32 ccw(c6403.47,488.32) v1@6394.08,478.93
NetLED20_1: LED20.1 R176.1 | length 6175.4
  Top Layer w4: v4@5133.06,298.06 cw(c5116.31,281.31) 5140,281.31 cw(c5163.69,281.31) v4@5146.94,298.06 ; v4@5135.89,300.89 cw(c5125.97,290.97) 5140,290.97 cw(c5154.03,290.97) v4@5144.11,300.89 ; v4(5140,305) 5140,205 5150,195 5239.45,195 5314.45,120 5830,120 5857.19,147.19 5857.19,337.23 5869.96,350 6020,350 6027.05,342.95 ; LED20.1@6022.9,334.59 ccw(c6016.55,342.95) 6027.05,342.95 ; LED20.1@6027.05,324.21 6027.05,342.95 ; LED20.1@6031.2,334.59 cw(c6037.55,342.95) 6027.05,342.95
  MidLayer1 w4: v4(3990,945) 4080,1035 4080,1235.04 4155,1310.04 4155,1560 4160,1565 4208.14,1565 4220,1576.86 4220,2070 4006.86,2283.14 4006.86,3041.1 4174.13,3208.37 v1(4253.52,3208.37) ; v4@3990,950.81 ccw(c3990,964.84) 3999.92,954.92 ccw(c4009.84,945) v4@3995.81,945 ; v4@3990,954.81 ccw(c3990,978.5) 4006.75,961.75 ccw(c4023.5,945) v4@3999.81,945 ; v1@4246.81,3201.66 ccw(c4230.59,3185.44) 4230.59,3208.37 ccw(c4230.59,3231.31) v1@4246.81,3215.09 ; v1@4249.64,3204.49 ccw(c4240.25,3195.1) 4240.25,3208.37 ccw(c4240.25,3221.65) v1@4249.64,3212.26
  MidLayer2 w4: v4(3990,945) 4080,945 4095,930 4406,930 4443,967 4790.37,967 5014,743.37 5014,524 4990,500 4920,500 4915.27,495.27 4915.27,429.73 4929.19,415.81 4958.36,415.81 5069.17,305 v4(5140,305) ; v4@3994.11,940.89 cw(c4004.03,930.97) 4004.03,945 cw(c4004.03,959.03) v4@3994.11,949.11 ; v4@3996.94,938.06 cw(c4013.69,921.31) 4013.69,945 cw(c4013.69,968.69) v4@3996.94,951.94 ; v4@5133.06,298.06 ccw(c5116.31,281.31) 5116.31,305 ccw(c5116.31,328.69) v4@5133.06,311.94 ; v4@5135.89,300.89 ccw(c5125.97,290.97) 5125.97,305 ccw(c5125.97,319.03) v4@5135.89,309.11
  Bottom Layer w4: v1@4254.52,3207.37 4366.19,3207.37 4373.52,3200.04 4378.82,3200.04 R176.1@4378.82,3198.75 ; v1@4257.41,3212.26 ccw(c4269.22,3224.07) 4269.22,3207.37 ; v1@4260.24,3201.66 cw(c4274.04,3187.85) 4274.04,3207.37 ; v1@4260.24,3215.09 ccw(c4278.87,3233.72) 4278.87,3207.37
NetLED20_3: LED20.3 R177.1 | length 5887.4
  Top Layer w4: v1(5948.94,185.44) 5949.5,186 5991,186 5999.67,194.67 LED20.3@5999.67,221.19 ; v1@5952.83,181.55 cw(c5963.56,170.82) 5963.56,186 ; v1@5952.83,189.33 ccw(c5960.87,197.37) 5960.87,186 ; v1@5955.66,178.72 cw(c5973.22,161.16) 5973.22,186 ; v1@5955.66,192.16 ccw(c5970.53,207.03) 5970.53,186 ; LED20.3@5995,211.04 cw(c5983.73,199.76) 5999.67,199.76 ; 5999.67,198.9 cw(c6016.84,198.9) LED20.3@6004.7,211.04 ; LED20.3@5999.67,221.19 5999.67,223.69 LED20.3@5999.67,221.19
  MidLayer1 w4: v1@4053.28,266.72 ccw(c4037.06,282.93) 4060,282.93 ccw(c4082.93,282.93) v1@4066.72,266.72 ; v1@4056.11,263.89 ccw(c4046.72,273.28) 4060,273.28 ccw(c4073.28,273.28) v1@4063.89,263.89 ; v1(4060,260) 4060,773 4145,858 4226.69,858 4262,893.31 4262,1318.31 4265.86,1322.17 4265.86,1553.23 4266,1553.37 4266,1571.5 4248.02,1589.48 4248.02,1740.65 4318.5,1811.12 4318.5,1838.88 4252,1905.38 4252,2086.63 4140.19,2198.44 4140.19,2436.35 4370,2666.16 4370,2814.14 4398.86,2843 4398.86,3024.71 v1(4373.52,3050.04) ; v1@4373.52,3040.54 cw(c4373.52,3017.61) 4389.74,3033.82 cw(c4405.96,3050.04) v1@4383.02,3050.04 ; v1@4373.52,3044.54 cw(c4373.52,3031.26) 4382.91,3040.65 cw(c4392.3,3050.04) v1@4379.02,3050.04
  MidLayer2 w4: v1@4053.28,253.28 cw(c4037.06,237.06) 4060,237.06 cw(c4082.93,237.06) v1@4066.72,253.28 ; v1@4056.11,256.11 cw(c4046.72,246.72) 4060,246.72 cw(c4073.28,246.72) v1@4063.89,256.11 ; v1(4060,260) 4060,225 4093.29,191.71 4615.19,191.71 4765.19,341.71 4998.52,341.71 5230.23,110 5334.09,110 5441.8,217.71 5937.29,217.71 5948.94,206.06 ; v1@5942.77,192.66 ccw(c5931.31,206.06) 5948.94,206.06 ; v1@5945.37,189.62 ccw(c5938.73,197.38) 5948.94,197.38 ccw(c5959.15,197.38) v1@5952.51,189.62 ; v1(5948.94,185.44) 5948.94,206.06 ; v1@5955.11,192.66 cw(c5966.57,206.06) 5948.94,206.06
  Bottom Layer w4: v1@4366.81,3056.76 ccw(c4350.59,3072.98) 4373.52,3072.98 ccw(c4396.46,3072.98) v1@4380.24,3056.76 ; v1@4369.64,3053.93 ccw(c4360.25,3063.32) 4373.52,3063.32 ccw(c4386.8,3063.32) v1@4377.41,3053.93 ; v1@4373.52,3049.64 cw(c4413.11,3049.64) R177.1@4385.35,3077.86 ; v1(4373.52,3050.04) 4373.52,3091.71 4378.82,3091.71 R177.1@4378.82,3085 ; v1@4373.52,3059.18 cw(c4403.73,3059.18) R177.1@4382.55,3080.72 ; 4373.52,3068.73 cw(c4394.34,3068.73) R177.1@4379.74,3083.57
NetLED20_4: LED20.4 R178.1 | length 4538.9
  Top Layer w4: v1@4348.52,3122.21 cw(c4348.52,3095.25) 4367.59,3114.31 ; v1@4348.52,3126.21 cw(c4348.52,3108.91) 4360.76,3121.14 ; v1@4350.19,3131.71 4406.86,3075.04 4406.86,1900.04 v1(4425.52,1881.37) ; v1@4358.02,3131.71 ccw(c4376.94,3131.71) 4363.56,3118.33 ; v1@4416.02,1881.37 ccw(c4393.09,1881.37) 4409.31,1897.59 ccw(c4425.52,1913.81) v1@4425.52,1890.87 ; v1@4420.02,1881.37 ccw(c4406.75,1881.37) 4416.13,1890.76 ccw(c4425.52,1900.15) v1@4425.52,1886.87 ; v1@5798.52,1257.21 cw(c5798.52,1234.27) 5814.74,1250.49 cw(c5830.96,1266.71) v1@5808.02,1266.71 ; v1@5798.52,1261.21 cw(c5798.52,1247.93) 5807.91,1257.32 cw(c5817.3,1266.71) v1@5804.02,1266.71 ; v1(5798.52,1266.71) 5831.67,1233.56 5831.67,1194.88 5990.19,1036.36 5990.19,927.37 6000.86,916.71 6000.86,818.02 6032,786.88 6032,368.94 6045,355.94 6045,307.31 6030.69,293 6006,293 5999.95,299.05 LED20.4@5999.95,324.21 ; LED20.4@5995.1,314.44 cw(c5983.39,302.73) 5999.95,302.73 cw(c6016.51,302.73) LED20.4@6004.8,314.44 ; LED20.4@5999.67,324.21 LED20.4@5999.67,323.83 ; LED20.4@5999.67,323.83 5999.67,321.33 LED20.4@5999.67,323.83
  MidLayer2 w4: v1(4425.52,1881.37) 4718.86,1881.37 4783.46,1816.77 4812.15,1816.77 4967.54,1661.38 4987.21,1641.71 5337.21,1641.71 5503.88,1475.04 5759.96,1475.04 5798.52,1436.48 v1(5798.52,1266.71) ; v1@4429.41,1877.49 cw(c4438.8,1868.1) 4438.8,1881.37 cw(c4438.8,1894.65) v1@4429.41,1885.26 ; v1@4432.24,1874.66 cw(c4448.46,1858.44) 4448.46,1881.37 cw(c4448.46,1904.31) v1@4432.24,1888.09 ; v1@5791.81,1273.43 ccw(c5775.59,1289.64) 5798.52,1289.64 ccw(c5821.46,1289.64) v1@5805.24,1273.43 ; v1@5794.64,1270.6 ccw(c5785.25,1279.99) 5798.52,1279.99 ccw(c5811.8,1279.99) v1@5802.41,1270.6
  Bottom Layer w4: v1(4348.52,3131.71) 4358.52,3141.71 ; 4367.08,3141.71 ccw(c4367.08,3151.69) R178.1@4374.74,3145.29 ; 4367.4,3141.71 cw(c4367.4,3131.79) R178.1@4374.83,3138.35 ; R178.1@4371.67,3147.85 cw(c4358.53,3158.84) 4358.53,3141.71 ; R178.1@4371.83,3135.71 ccw(c4358.53,3123.95) 4358.53,3141.71 ; R178.1@4378.82,3141.71 4358.52,3141.71
NetLED21_1: LED21.1 R179.1 | length 5944.2
  Top Layer w4: v1@4150.14,3051.66 cw(c4133.92,3035.44) 4156.86,3035.44 cw(c4179.79,3035.44) v1@4163.57,3051.66 ; v1@4152.97,3054.49 cw(c4143.58,3045.1) 4156.86,3045.1 cw(c4170.14,3045.1) v1@4160.75,3054.49 ; v1(4156.86,3058.37) 4156.86,2916.71 4382.19,2691.37 4382.19,1267.19 4340.04,1225.04 v1(4290.19,1225.04) ; v1@4294.08,1221.15 cw(c4303.47,1211.76) 4303.47,1225.04 cw(c4303.47,1238.32) v1@4294.08,1228.93 ; v1@4296.91,1218.32 cw(c4313.13,1202.11) 4313.13,1225.04 cw(c4313.13,1247.98) v1@4296.91,1231.76 ; v1@6069.86,702.54 cw(c6069.86,679.61) 6086.07,695.82 cw(c6102.29,712.04) v1@6079.36,712.04 ; v1@6069.86,706.54 cw(c6069.86,693.26) 6079.25,702.65 cw(c6088.64,712.04) v1@6075.36,712.04 ; v1(6069.86,712.04) 6148.52,633.37 6148.52,595 6138.48,584.95 6138.48,348.33 LED21.1@6138.48,321.33 ; LED21.1@6133.45,333.98 ccw(c6121.31,346.12) 6138.48,346.12 ; 6138.48,345.25 ccw(c6154.42,345.25) LED21.1@6143.15,333.98
  MidLayer1 w4: v1(4156.86,3058.37) 4290.19,3191.71 4290.19,3231.37 v1(4294.19,3235.37) ; v1@4156.86,3063.87 ccw(c4156.86,3077.15) 4166.25,3067.76 ccw(c4175.64,3058.37) v1@4162.36,3058.37 ; v1@4156.86,3067.87 ccw(c4156.86,3090.81) 4173.07,3074.59 ccw(c4189.29,3058.37) v1@4166.36,3058.37 ; v1@4287.47,3228.66 cw(c4280.91,3222.1) 4290.19,3222.1 cw(c4307.47,3222.1) v1@4295.25,3234.31 ; 4290.19,3202.78 cw(c4326.78,3202.78) v1@4300.91,3228.66 ; 4290.19,3212.44 cw(c4317.13,3212.44) v1@4298.08,3231.49
  MidLayer2 w4: v1@4290.19,1215.54 cw(c4290.19,1192.61) 4306.41,1208.82 cw(c4322.63,1225.04) v1@4299.69,1225.04 ; v1@4290.19,1219.54 cw(c4290.19,1206.26) 4299.58,1215.65 cw(c4308.97,1225.04) v1@4295.69,1225.04 ; v1(4290.19,1225.04) 4406.86,1108.37 4801.5,1108.37 4810.5,1099.37 5274.19,1099.37 5298.52,1075.04 5298.52,875.04 5322.69,850.87 6038,850.87 6069.86,819.02 v1(6069.86,712.04) ; v1@6063.14,718.76 ccw(c6046.92,734.98) 6069.86,734.98 ccw(c6092.79,734.98) v1@6076.57,718.76 ; v1@6065.97,715.93 ccw(c6056.58,725.32) 6069.86,725.32 ccw(c6083.14,725.32) v1@6073.75,715.93
  Bottom Layer w4: v1@4284.69,3235.37 ccw(c4261.76,3235.37) 4277.97,3251.59 ccw(c4294.19,3267.81) v1@4294.19,3244.87 ; v1@4288.69,3235.37 ccw(c4275.41,3235.37) 4284.8,3244.76 ccw(c4294.19,3254.15) v1@4294.19,3240.87 ; v1(4294.19,3235.37) 4271.19,3258.37 4190.19,3258.37 4172.86,3275.71 4172.86,3447.41 4192.15,3466.71 4215,3466.71 4230,3451.71 4230,3400 4260.63,3369.37 R179.1@4378.82,3369.38 ; R179.1@4371.53,3363.57 ccw(c4359.5,3354.01) 4359.5,3369.37 ccw(c4359.5,3384.74) R179.1@4371.52,3375.18
NetLED21_3: LED21.3 R180.1 | length 5003.8
  Top Layer w4: v1@4339.02,3225.04 cw(c4316.09,3225.04) 4332.31,3208.82 cw(c4348.52,3192.61) v1@4348.52,3215.54 ; v1@4343.02,3225.04 cw(c4329.75,3225.04) 4339.13,3215.65 cw(c4348.52,3206.26) v1@4348.52,3219.54 ; v1(4348.52,3225.04) 4315.19,3191.71 4315.19,2781 4398.52,2697.67 4398.52,1678.02 4518.17,1558.37 v1(4576.52,1558.37) ; v1@4569.81,1551.66 ccw(c4553.59,1535.44) 4553.59,1558.37 ccw(c4553.59,1581.31) v1@4569.81,1565.09 ; v1@4572.64,1554.49 ccw(c4563.25,1545.1) 4563.25,1558.37 ccw(c4563.25,1571.65) v1@4572.64,1562.26 ; LED21.3@6106.25,230.58 ccw(c6094.54,242.29) 6111.1,242.29 ccw(c6127.65,242.29) LED21.3@6115.95,230.58 ; LED21.3@6111.1,220.81 6111.1,265 6061,315.1 6061,340 6061,362.56 6048,375.56 6048,534.52 6071.35,557.87 v1(6123.52,610.04) ; v1@6114.02,610.04 cw(c6091.09,610.04) 6107.31,593.82 cw(c6123.52,577.61) v1@6123.52,600.54 ; v1@6118.02,610.04 cw(c6104.75,610.04) 6114.14,600.65 cw(c6123.52,591.26) v1@6123.52,604.54
  MidLayer2 w4: v1(4576.52,1558.37) 4917.56,1558.37 5214.69,1261.25 5214.69,1206.15 5230.84,1190 5566.06,1190 5597.35,1221.29 5673.69,1221.29 5710.76,1184.21 5907.95,1184.21 5932.94,1209.21 6025.79,1209.21 6097.36,1137.64 6097.36,1000.6 6115.87,982.09 6145.26,952.7 6145.26,631.77 v1(6123.52,610.04) ; v1@4580.41,1554.49 cw(c4589.8,1545.1) 4589.8,1558.37 cw(c4589.8,1571.65) v1@4580.41,1562.26 ; v1@4583.24,1551.66 cw(c4599.46,1535.44) 4599.46,1558.37 cw(c4599.46,1581.31) v1@4583.24,1565.09 ; v1@6123.52,615.54 ccw(c6123.52,628.82) 6132.91,619.43 ccw(c6142.3,610.04) v1@6129.02,610.04 ; v1@6123.52,619.54 ccw(c6123.52,642.48) 6139.74,626.26 ccw(c6155.96,610.04) v1@6133.02,610.04
  Bottom Layer w4: v1@4343.68,3233.22 ccw(c4338.65,3241.71) 4348.52,3241.71 ; v1(4348.52,3225.04) 4348.52,3241.71 ; v1@4353.36,3233.22 cw(c4358.39,3241.71) 4348.52,3241.71 ; R180.1@4370.81,3250.86 ccw(c4362.44,3245.89) 4362.44,3255.62 ; R180.1@4370.81,3260.39 cw(c4362.44,3265.36) 4362.44,3255.62 ; R180.1@4378.82,3255.62 4362.44,3255.62 ; 4348.52,3241.71 4362.44,3255.62
NetLED21_4: LED21.4 R181.1 | length 5109.8
  Top Layer w4: v1@4200.14,3293.99 cw(c4183.92,3277.77) 4206.86,3277.77 cw(c4229.79,3277.77) v1@4213.57,3293.99 ; v1@4202.97,3296.82 cw(c4193.58,3287.43) 4206.86,3287.43 cw(c4220.14,3287.43) v1@4210.75,3296.82 ; v1(4206.86,3300.71) 4206.86,2878.02 4390.19,2694.69 4390.19,1675.04 4556.86,1508.37 v1(4556.86,1228.71) ; v1@4550.14,1235.43 ccw(c4533.92,1251.64) 4556.86,1251.64 ccw(c4579.79,1251.64) v1@4563.57,1235.43 ; v1@4552.97,1232.6 ccw(c4543.58,1241.99) 4556.86,1241.99 ccw(c4570.14,1241.99) v1@4560.75,1232.6 ; v1@6084.29,517.6 cw(c6074.59,505.38) 6090.19,505.38 ; v1(6090.19,525.04) 6090.19,505.37 ; v1@6096.1,517.6 ccw(c6105.79,505.38) 6090.19,505.38 ; LED21.4@6106.35,333.98 ccw(c6095.31,345.01) 6110.92,345.01 ; LED21.4@6110.92,321.33 6110.92,484.65 6090.19,505.37 ; 6110.92,346.36 ccw(c6128.43,346.36) LED21.4@6116.05,333.98
  MidLayer2 w4: v1@4556.86,1219.21 cw(c4556.86,1196.27) 4573.07,1212.49 cw(c4589.29,1228.71) v1@4566.36,1228.71 ; v1@4556.86,1223.21 cw(c4556.86,1209.93) 4566.25,1219.32 cw(c4575.64,1228.71) v1@4562.36,1228.71 ; v1(4556.86,1228.71) 4668.86,1116.71 4804.48,1116.71 4813.82,1107.37 5278.86,1107.37 5306.52,1079.71 5306.52,878.48 5326.13,858.87 6041.32,858.87 6090.19,810 v1(6090.19,525.04) ; v1@6083.47,531.76 ccw(c6067.26,547.98) 6090.19,547.98 ccw(c6113.13,547.98) v1@6096.91,531.76 ; v1@6086.3,528.93 ccw(c6076.91,538.32) 6090.19,538.32 ccw(c6103.47,538.32) v1@6094.08,528.93
  Bottom Layer w4: v1(4206.86,3300.71) 4278.21,3300.71 4290,3312.5 R181.1@4378.82,3312.5 ; v1@4210.75,3296.82 cw(c4220.14,3287.43) 4220.14,3300.71 cw(c4220.14,3313.99) v1@4210.75,3304.6 ; v1@4213.57,3293.99 cw(c4229.79,3277.77) 4229.79,3300.71 cw(c4229.79,3323.64) v1@4213.57,3307.43 ; R181.1@4372.23,3305.91 ccw(c4356.32,3290) 4356.32,3312.5 ccw(c4356.32,3335) R181.1@4372.23,3319.09 ; R181.1@4375.06,3308.74 ccw(c4365.98,3299.66) 4365.98,3312.5 ccw(c4365.98,3325.34) R181.1@4375.06,3316.26
NetLED22_1: LED22.1 R182.1 | length 5774.6
  Top Layer w4: v1@4240.19,2715.54 cw(c4240.19,2692.61) 4256.41,2708.82 cw(c4272.63,2725.04) v1@4249.69,2725.04 ; v1@4240.19,2719.54 cw(c4240.19,2706.26) 4249.58,2715.65 cw(c4258.97,2725.04) v1@4245.69,2725.04 ; v1(4240.19,2725.04) 4298.52,2666.71 4298.52,1967.47 4329.46,1936.54 4329.46,1908.79 4320,1899.33 v1(4320,1285) ; v1@4313.28,1291.72 ccw(c4297.06,1307.93) 4320,1307.93 ccw(c4342.93,1307.93) v1@4326.72,1291.72 ; v1@4316.11,1288.89 ccw(c4306.72,1298.28) 4320,1298.28 ccw(c4333.28,1298.28) v1@4323.89,1288.89 ; v1@6241.81,509.99 cw(c6225.59,493.77) 6248.52,493.77 cw(c6271.46,493.77) v1@6255.24,509.99 ; v1@6244.64,512.82 cw(c6235.25,503.43) 6248.52,503.43 cw(c6261.8,503.43) v1@6252.41,512.82 ; LED22.1@6244.69,333.98 ccw(c6235.45,343.23) 6248.52,343.23 ; 6248.52,338.49 ccw(c6258.9,338.49) LED22.1@6251.56,331.15 ; 6248.52,348.15 ccw(c6268.56,348.15) LED22.1@6254.39,333.98 ; v1(6248.52,516.71) 6248.52,322.52 LED22.1@6249.72,321.33
  MidLayer1 w4: v1@4233.47,2731.76 ccw(c4217.26,2747.98) 4240.19,2747.98 ccw(c4263.13,2747.98) v1@4246.91,2731.76 ; v1@4236.3,2728.93 ccw(c4226.91,2738.32) 4240.19,2738.32 ccw(c4253.47,2738.32) v1@4244.08,2728.93 ; v1(4240.19,2725.04) 4240.19,2968.73 4381.86,3110.39 4381.86,3341.71 4344.52,3379.04 4344.52,3549.71 v1(4373.52,3578.71) ; v1@4364.02,3578.71 cw(c4341.09,3578.71) 4357.31,3562.49 cw(c4373.52,3546.27) v1@4373.52,3569.21 ; v1@4368.02,3578.71 cw(c4354.75,3578.71) 4364.14,3569.32 cw(c4373.52,3559.93) v1@4373.52,3573.21
  MidLayer2 w4: v1@4320,1275.5 cw(c4320,1252.56) 4336.22,1268.78 cw(c4352.43,1285) v1@4329.5,1285 ; v1@4320,1279.5 cw(c4320,1266.22) 4329.39,1275.61 cw(c4338.78,1285) v1@4325.5,1285 ; v1(4320,1285) 4338.63,1266.37 4885.17,1266.37 4984.84,1166.71 5230,1166.71 5245.29,1182 5569.37,1182 5600.66,1213.29 5670.38,1213.29 5707.45,1176.21 5911.26,1176.21 5935.05,1200 6023.69,1200 6089.36,1134.33 6089.36,997.29 6098.52,988.12 6098.52,545.71 6127.52,516.71 v1(6248.52,516.71) ; v1@6241.81,509.99 ccw(c6225.59,493.77) 6225.59,516.71 ccw(c6225.59,539.64) v1@6241.81,523.43 ; v1@6244.64,512.82 ccw(c6235.25,503.43) 6235.25,516.71 ccw(c6235.25,529.99) v1@6244.64,520.6
  Bottom Layer w4: v1@4368.98,3570.37 cw(c4364.8,3562.71) 4373.52,3562.71 ; v1(4373.52,3578.71) 4373.52,3562.71 ; R182.1@4373.84,3548.37 ccw(c4368.12,3557.41) 4378.82,3557.41 ; v1@4378.07,3570.37 ccw(c4382.25,3562.71) 4373.52,3562.71 ; R182.1@4378.82,3540 4378.82,3557.41 ; R182.1@4383.8,3548.37 cw(c4389.52,3557.41) 4378.82,3557.41 ; 4373.52,3562.71 4378.82,3557.41
NetLED22_3: LED22.3 R183.1 | length 6073.1
  Top Layer w4: v1(6190.19,207.37) 6203.62,220.81 LED22.3@6222.34,220.81 ; LED22.3@6217.49,215.96 ccw(c6205.79,204.25) 6205.79,220.81 ccw(c6205.79,237.36) LED22.3@6217.49,225.66 ; LED22.3@6220.81,222.34 LED22.3@6222.16,223.69
  MidLayer1 w4: 4273.86,1549.92 4273.86,1318.86 4270,1315 4270,890 4230,850 4148.31,850 4085,786.69 4085,240 4135,190 4785,190 4850,255 5048.69,255 5203.69,100 5610,100 5737,227 6170.56,227 v1(6190.19,207.37) ; 4274,1550.06 4274,1574.82 4256.02,1592.79 4256.02,1737.33 4311.52,1792.83 4326.5,1807.81 4326.5,1842.19 4260,1908.69 4260,2089.94 4198.52,2151.42 4198.52,2483.37 4406.86,2691.71 4406.86,3075 ; v1@4375.14,3391.66 cw(c4358.92,3375.44) 4381.86,3375.44 cw(c4404.79,3375.44) v1@4388.57,3391.66 ; v1@4377.97,3394.49 cw(c4368.58,3385.1) 4381.86,3385.1 cw(c4395.14,3385.1) v1@4385.75,3394.49 ; v1(4381.86,3398.37) 4381.86,3365.35 4398.52,3348.69 4398.52,3106.48 4406.86,3098.14 4406.86,3075 ; 4406.86,3085 4406.86,3075 ; v1@6180.69,207.37 ccw(c6157.76,207.37) 6173.97,223.59 ccw(c6190.19,239.81) v1@6190.19,216.87 ; v1@6184.69,207.37 ccw(c6171.41,207.37) 6180.8,216.76 ccw(c6190.19,226.15) v1@6190.19,212.87
  Bottom Layer w4: R183.1@4372.62,3418.8 cw(c4354.29,3398.21) v1@4381.86,3398.21 ; v1@4375.14,3405.09 ccw(c4358.92,3421.31) 4381.86,3421.31 ccw(c4404.79,3421.31) v1@4388.57,3405.09 ; R183.1@4375.28,3421.79 cw(c4362.23,3407.13) v1@4381.86,3407.13 ; v1@4377.97,3402.26 ccw(c4368.58,3411.65) 4381.86,3411.65 ccw(c4395.14,3411.65) v1@4385.75,3402.26 ; R183.1@4378.82,3425.04 R183.1@4378.82,3426.25 ; R183.1@4378.86,3425.04 4381.86,3422.04 v1(4381.86,3398.37) ; 4381.86,3410.6 cw(c4393.98,3410.6) R183.1@4385.41,3419.17
NetLED22_4: LED22.4 R184.1 | length 5213.2
  Top Layer w4: v1@4373.52,3445.54 cw(c4373.52,3422.61) 4389.74,3438.82 cw(c4405.96,3455.04) v1@4383.02,3455.04 ; v1@4373.52,3449.54 cw(c4373.52,3436.26) 4382.91,3445.65 cw(c4392.3,3455.04) v1@4379.02,3455.04 ; v1(4373.52,3455.04) 4415.19,3413.37 4415.19,3388.73 4398.52,3372.06 4398.52,3158.37 4491.19,3065.71 4491.19,2771.19 4455,2735 4455,2636.86 4465.86,2626 4465.86,2139 4456.86,2130 v1(4456.86,1925.04) ; v1@4450.14,1931.76 ccw(c4433.92,1947.98) 4456.86,1947.98 ccw(c4479.79,1947.98) v1@4463.57,1931.76 ; v1@4452.97,1928.93 ccw(c4443.58,1938.32) 4456.86,1938.32 ccw(c4470.14,1938.32) v1@4460.75,1928.93 ; v1@5989.02,1475.04 cw(c5966.09,1475.04) 5982.31,1458.82 cw(c5998.52,1442.61) v1@5998.52,1465.54 ; v1@5993.02,1475.04 cw(c5979.75,1475.04) 5989.14,1465.65 cw(c5998.52,1456.26) v1@5998.52,1469.54 ; v1(5998.52,1475.04) 5973.52,1450.04 5881.86,1450.04 5873.52,1441.71 5873.52,1400.04 6040.19,1233.37 6040.19,898.68 6222.16,716.71 LED22.4@6222.16,321.33 ; LED22.4@6217.59,333.98 ccw(c6206.56,345.01) 6222.16,345.01 ; 6222.16,346.36 ccw(c6239.67,346.36) LED22.4@6227.29,333.98
  MidLayer2 w4: v1(4456.86,1925.04) 4473.86,1942.04 4674.98,1942.04 4687.83,1929.19 4736.04,1929.19 4740.19,1925.04 5006.86,1658.37 5398.52,1658.37 5565.19,1491.71 5981.86,1491.71 v1(5998.52,1475.04) ; v1@4456.86,1930.54 ccw(c4456.86,1943.82) 4466.25,1934.43 ccw(c4475.64,1925.04) v1@4462.36,1925.04 ; v1@4456.86,1934.54 ccw(c4456.86,1957.48) 4473.07,1941.26 ccw(c4489.29,1925.04) v1@4466.36,1925.04 ; v1@5989.02,1475.04 ccw(c5966.09,1475.04) 5982.31,1491.26 ccw(c5998.52,1507.48) v1@5998.52,1484.54 ; v1@5993.02,1475.04 ccw(c5979.75,1475.04) 5989.14,1484.43 ccw(c5998.52,1493.82) v1@5998.52,1480.54
  Bottom Layer w4: v1@4368.15,3462.88 ccw(c4354.27,3483.12) 4378.82,3483.12 v1@4378.82,3460.34 ; v1@4370.41,3459.58 ccw(c4359.48,3475.53) R184.1@4378.82,3475.53 ; R184.1@4372.27,3476 cw(c4356.81,3460.34) v1@4378.82,3460.34 ; v1@4372.68,3456.28 ccw(c4364.68,3467.94) 4378.82,3467.94 ; v1(4373.52,3455.04) v1@4378.82,3460.34 ; R184.1@4375.08,3478.85 cw(c4366.26,3469.91) 4378.82,3469.91 cw(c4391.38,3469.91) R184.1@4382.56,3478.85 ; R184.1@4385.37,3476 ccw(c4400.83,3460.34) v1@4378.82,3460.34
